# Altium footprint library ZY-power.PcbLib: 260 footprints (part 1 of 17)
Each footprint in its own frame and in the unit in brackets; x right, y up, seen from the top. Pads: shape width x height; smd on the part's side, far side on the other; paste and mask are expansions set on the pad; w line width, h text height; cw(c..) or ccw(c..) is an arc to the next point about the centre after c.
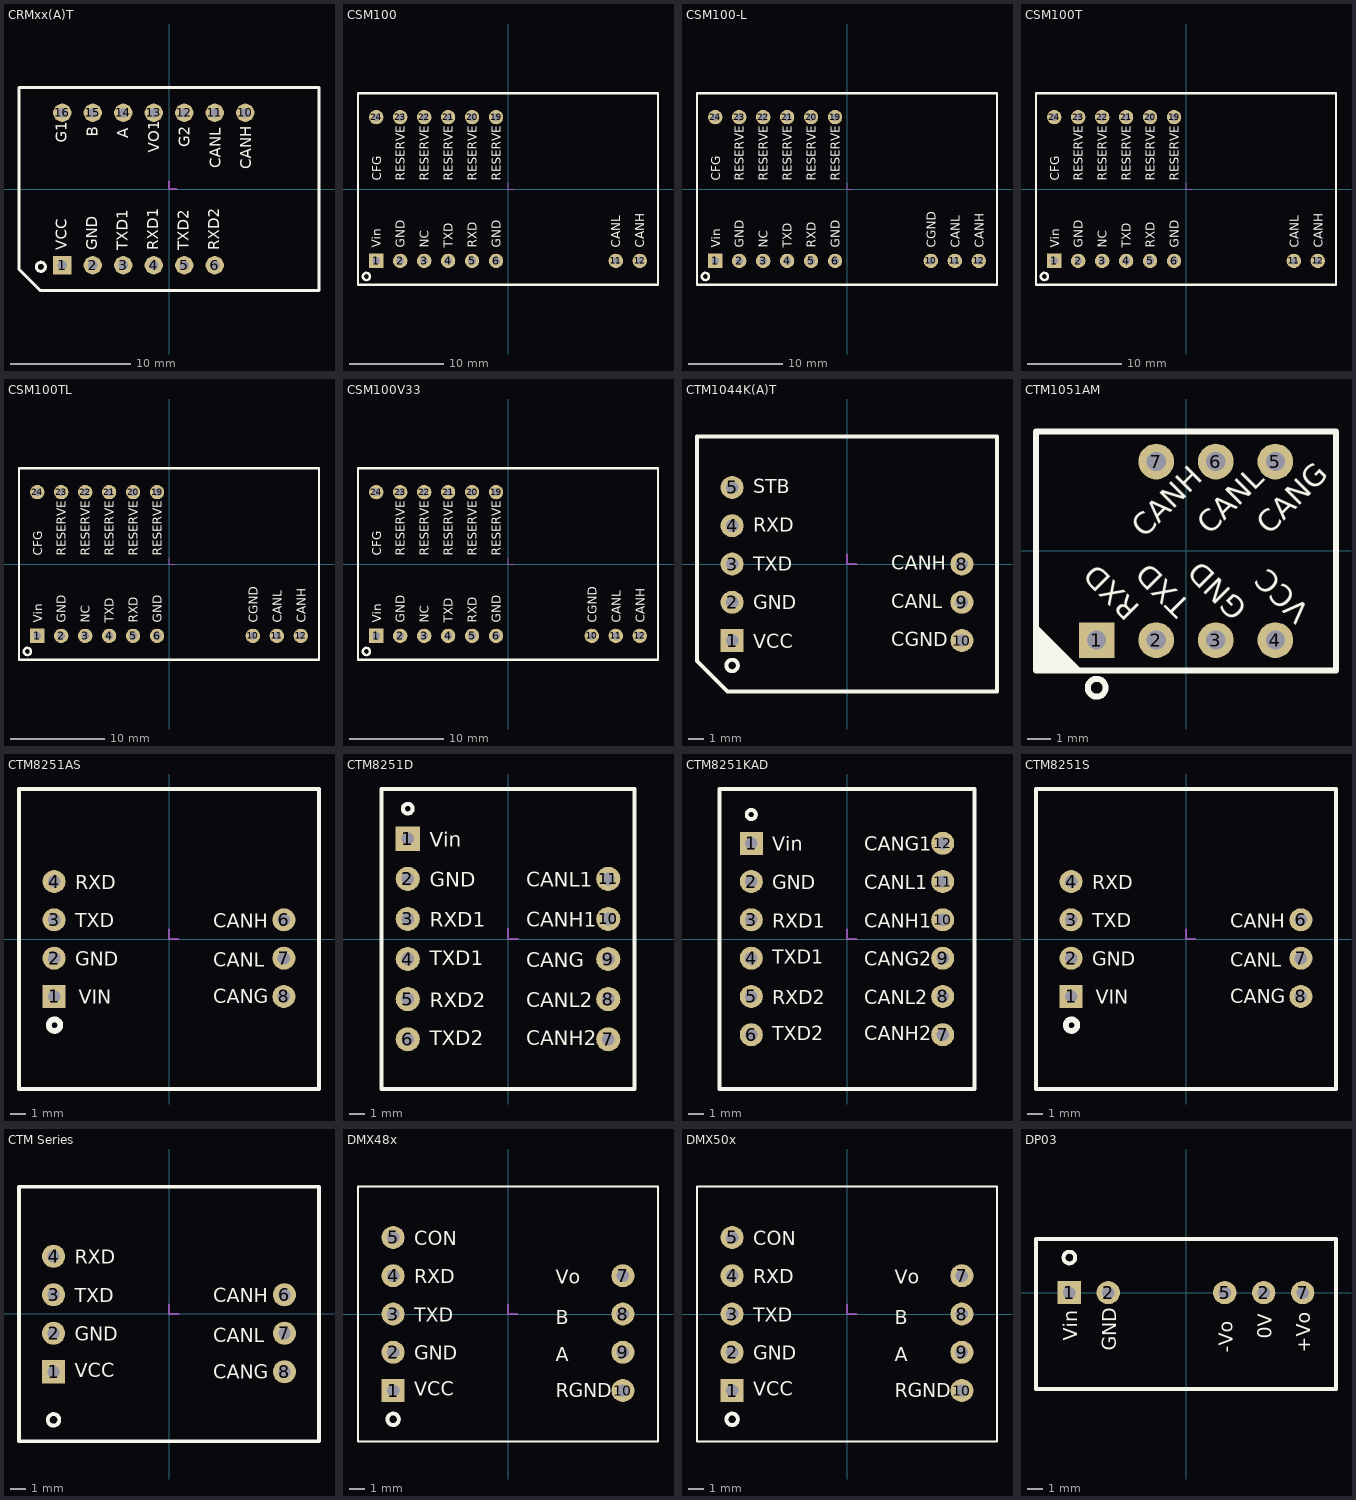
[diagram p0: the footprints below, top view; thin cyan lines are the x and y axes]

## CRMxx(A)T [mil]
height 279.53
pads (13):
  rect 60x60 hole 32: 1(-350,-250)
  round 60 hole 32: 2(-250,-250) 3(-150,-250) 4(-50,-250) 5(50,-250) 6(150,-250) 10(250,250) 11(150,250) 12(50,250) 13(-50,250) 14(-150,250) 15(-250,250) 16(-350,250)
Top Overlay:
  circle w10: c-420,-255 r15
  lines w10: -491.73,-263.27 -422.32,-332.68 491.73,-332.68 491.73,332.68 -491.73,332.68 -491.73,-263.27
  text "G1" at -335,152.07 h36
  text "B" at -234.17,170.58 h36
  text "A" at -133.33,167.15 h36
  text "VO1" at -32.5,118.13 h36
  text "G2" at 68.33,136.64 h36
  text "CANL" at 169.17,68.43 h36
  text "RXD2" at 165,-200 h36
  text "TXD2" at 65,-200 h36
  text "RXD1" at -35,-200 h36
  text "TXD1" at -135,-200 h36
  text "GND" at -235,-200 h36
  text "CANH" at 270,65 h36
  text "VCC" at -335,-200 h36
Mechanical 15:
  lines w5: 0,25 0,0 25,0

## CSM100 [mil] "嵌入式CAN-bus接口芯片"
height 370.08
pads (14):
  rect 60x60 hole 32: 1(-550,-300)
  round 60 hole 32: 2(-450,-300) 3(-350,-300) 4(-250,-300) 5(-150,-300) 6(-50,-300) 11(450,-300) 12(550,-300) 19(-50,300) 20(-150,300) 21(-250,300) 22(-350,300) 23(-450,300) 24(-550,300)
Top Overlay:
  circle w10: c-590.98,-365 r15
  lines w10: -625.98,-399.61 625.98,-399.61 625.98,399.61 -625.98,399.61 -625.98,-399.61
  text "Vin" at -531,-245 h36
  text "GND" at -431,-245 h36
  text "NC" at -331,-245 h36
  text "TXD" at -231,-245 h36
  text "RXD" at -131,-245 h36
  text "CANL" at 469,-245 h36
  text "CANH" at 569,-245 h36
  text "RESERVE" at -30,35 h36
  text "GND" at -31,-245 h36
  text "RESERVE" at -130,35 h36
  text "RESERVE" at -230,35 h36
  text "RESERVE" at -330,35 h36
  text "CFG" at -530,35 h36
  text "RESERVE" at -430,35 h36
Mechanical 15:
  lines w5: 0,25 0,0 25,0

## CSM100-L [mil]
pads (15):
  rect 60x60 hole 32: 1(-550,-300)
  round 60 hole 32: 2(-450,-300) 3(-350,-300) 4(-250,-300) 5(-150,-300) 6(-50,-300) 10(350,-300) 11(450,-300) 12(550,-300) 19(-50,300) 20(-150,300) 21(-250,300) 22(-350,300) 23(-450,300) 24(-550,300)
Top Overlay:
  circle w10: c-590.98,-365 r15
  lines w10: -625.98,-399.61 -625.98,399.61 625.98,399.61 625.98,-399.61 -625.98,-399.61
  text "CGND" at 370,-245 h36
  text "CFG" at -530,35 h36
  text "RESERVE" at -330,35 h36
  text "RESERVE" at -230,35 h36
  text "RESERVE" at -130,35 h36
  text "GND" at -30,-245 h36
  text "RESERVE" at -30,35 h36
  text "CANH" at 570,-245 h36
  text "CANL" at 470,-245 h36
  text "RXD" at -130,-245 h36
  text "TXD" at -230,-245 h36
  text "NC" at -330,-245 h36
  text "GND" at -430,-245 h36
  text "Vin" at -530,-245 h36
  text "RESERVE" at -430,35 h36
Mechanical 15:
  lines w5: 0,25 0,0 25,0

## CSM100T [mil]
pads (14):
  rect 60x60 hole 32: 1(-550,-300)
  round 60 hole 32: 2(-450,-300) 3(-350,-300) 4(-250,-300) 5(-150,-300) 6(-50,-300) 11(450,-300) 12(550,-300) 19(-50,300) 20(-150,300) 21(-250,300) 22(-350,300) 23(-450,300) 24(-550,300)
Top Overlay:
  circle w10: c-590.98,-365 r15
  lines w10: -625.98,-399.61 625.98,-399.61 625.98,399.61 -625.98,399.61 -625.98,-399.61
  text "Vin" at -530,-245 h36
  text "GND" at -430,-245 h36
  text "NC" at -330,-245 h36
  text "TXD" at -230,-245 h36
  text "RXD" at -130,-245 h36
  text "CANL" at 470,-245 h36
  text "CANH" at 570,-245 h36
  text "RESERVE" at -30,35 h36
  text "GND" at -30,-245 h36
  text "RESERVE" at -130,35 h36
  text "RESERVE" at -230,35 h36
  text "RESERVE" at -330,35 h36
  text "CFG" at -530,35 h36
  text "RESERVE" at -430,35 h36
Mechanical 15:
  lines w5: 0,25 0,0 25,0

## CSM100TL [mil]
height 255.91
pads (15):
  rect 60x60 hole 32: 1(-550,-300)
  round 60 hole 32: 2(-450,-300) 3(-350,-300) 4(-250,-300) 5(-150,-300) 6(-50,-300) 10(350,-300) 11(450,-300) 12(550,-300) 19(-50,300) 20(-150,300) 21(-250,300) 22(-350,300) 23(-450,300) 24(-550,300)
Top Overlay:
  circle w10: c-590.98,-365 r15
  lines w10: -625.98,-399.61 625.98,-399.61 625.98,399.61 -625.98,399.61 -625.98,-399.61
  text "RESERVE" at -430,35 h36
  text "Vin" at -530,-245 h36
  text "GND" at -430,-245 h36
  text "NC" at -330,-245 h36
  text "TXD" at -230,-245 h36
  text "RXD" at -130,-245 h36
  text "CANL" at 470,-245 h36
  text "CANH" at 570,-245 h36
  text "RESERVE" at -30,35 h36
  text "GND" at -30,-245 h36
  text "RESERVE" at -130,35 h36
  text "RESERVE" at -230,35 h36
  text "RESERVE" at -330,35 h36
  text "CFG" at -530,35 h36
  text "CGND" at 370,-245 h36
Mechanical 15:
  lines w5: 0,25 0,0 25,0

## CSM100V33 [mil]
pads (15):
  rect 60x60 hole 32: 1(-550,-300)
  round 60 hole 32: 2(-450,-300) 3(-350,-300) 4(-250,-300) 5(-150,-300) 6(-50,-300) 10(350,-300) 11(450,-300) 12(550,-300) 19(-50,300) 20(-150,300) 21(-250,300) 22(-350,300) 23(-450,300) 24(-550,300)
Top Overlay:
  circle w10: c-590.98,-365 r15
  lines w10: -625.98,-399.61 625.98,-399.61 625.98,399.61 -625.98,399.61 -625.98,-399.61
  text "RESERVE" at -430,35 h36
  text "Vin" at -530,-245 h36
  text "GND" at -430,-245 h36
  text "NC" at -330,-245 h36
  text "TXD" at -230,-245 h36
  text "RXD" at -130,-245 h36
  text "CANL" at 470,-245 h36
  text "CANH" at 570,-245 h36
  text "RESERVE" at -30,35 h36
  text "GND" at -30,-245 h36
  text "RESERVE" at -130,35 h36
  text "RESERVE" at -230,35 h36
  text "RESERVE" at -330,35 h36
  text "CFG" at -530,35 h36
  text "CGND" at 370,-245 h36
Mechanical 15:
  lines w5: 0,25 0,0 25,0

## CTM1044K(A)T [mil]
height 277.56
pads (8):
  rect 60x60 hole 32: 1(-300,-200)
  round 60 hole 32: 2(-300,-100) 3(-300,0) 4(-300,100) 5(-300,200) 8(300,0) 9(300,-100) 10(300,-200)
Top Overlay:
  circle w10: c-300,-265 r15
  lines w10: -391.73,-253.27 -391.73,332.68 391.73,332.68 391.73,-332.68 -312.32,-332.68 -391.73,-253.27
  text "VCC" at -245,-220 h36
  text "GND" at -245,-118.75 h36
  text "TXD" at -245,-17.5 h36
  text "RXD" at -245,83.75 h36
  text "CANH" at 115,-15 h36
  text "CANL" at 115,-115 h36
  text "CGND" at 115,-215 h36
  text "STB" at -245,185 h36
Mechanical 15:
  lines w5: 0,25 0,0 25,0

## CTM1051AM [mil]
height 303.15
pads (7):
  rect 60x60 hole 32: 1(-150,-150)
  round 60 hole 32: 2(-50,-150) 3(50,-150) 4(150,-150) 5(150,150) 6(50,150) 7(-50,150)
Top Overlay:
  circle w10: c-150,-230 r15
  region: -251.97,-200.79 -174.21,-200.79 -251.97,-123.04
  lines w10: -251.97,-200.79 251.97,-200.79 251.97,200.79 -251.97,200.79 -251.97,-200.79
  text "VCC" at 210,-100 h36
  text "GND" at 105,-95 h36
  text "TXD" at 10,-90 h36
  text "RXD" at -75,-95 h36
  text "CANH" at -70,20 h36
  text "CANL" at 40,25 h36
  text "CANG" at 140,25 h36

## CTM8251AS [mil]
height 196.85
pads (7):
  rect 60x60 hole 32: 1(-300,-150)
  round 60 hole 32: 2(-300,-50) 3(-300,50) 4(-300,150) 6(300,50) 7(300,-50) 8(300,-150)
Top Overlay:
  circle w15: c-299,-225 r15
  lines w10: -391.73,-391.73 -391.73,391.73 391.73,391.73 391.73,-391.73 -391.73,-391.73
  text "CANG" at 115,-168 h36
  text "CANL" at 115,-73 h36
  text "CANH" at 115,30 h36
  text "RXD" at -245,130 h36
  text "TXD" at -245,30.33 h36
  text "GND" at -245,-69.33 h36
  text "VIN" at -236,-169 h36
Mechanical 15:
  lines w5: 0,25 0,0 25,0

## CTM8251D [mil]
pads (11):
  rect 60x60 hole 32: 1(-250,250)
  round 60 hole 32: 2(-250,150) 3(-250,50) 4(-250,-50) 5(-250,-150) 6(-250,-250) 7(250,-250) 8(250,-150) 9(250,-50) 10(250,50) 11(250,150)
Top Overlay:
  circle w10: c-250,325 r12
  lines w10: -314.96,-374.02 -314.96,374.02 314.96,374.02 314.96,-374.02 -314.96,-374.02
  text "RXD2" at -195,-170 h36
  text "TXD2" at -195,-265 h36
  text "CANH2" at 45,-265 h36
  text "CANL2" at 45,-170 h36
  text "TXD1" at -195,-65 h36
  text "RXD1" at -195,30 h36
  text "GND" at -195,130 h36
  text "Vin" at -195,230 h36
  text "CANL1" at 45,130 h36
  text "CANH1" at 45,30 h36
  text "CANG" at 45,-70 h36
Mechanical 15:
  lines w5: 0,25 0,0 25,0

## CTM8251KAD [mil]
pads (12):
  rect 60x60 hole 32: 1(-250,250)
  round 60 hole 32: 2(-250,150) 3(-250,50) 4(-250,-50) 5(-250,-150) 6(-250,-250) 7(250,-250) 8(250,-150) 9(250,-50) 10(250,50) 11(250,150) 12(250,250)
Top Overlay:
  circle w10: c-250,325 r12
  lines w10: -332.68,-391.73 -332.68,391.73 332.68,391.73 332.68,-391.73 -332.68,-391.73
  text "RXD2" at -195,-170 h36
  text "TXD2" at -195,-265 h36
  text "CANH2" at 45,-265 h36
  text "CANL2" at 45,-170 h36
  text "TXD1" at -195,-65 h36
  text "RXD1" at -195,30 h36
  text "GND" at -195,130 h36
  text "Vin" at -195,230 h36
  text "CANL1" at 45,130 h36
  text "CANH1" at 45,30 h36
  text "CANG2" at 45,-70 h36
  text "CANG1" at 45,230 h36
Mechanical 15:
  lines w5: 0,25 0,0 25,0

## CTM8251S [mil]
height 196.85
pads (7):
  rect 60x60 hole 32: 1(-300,-150)
  round 60 hole 32: 2(-300,-50) 3(-300,50) 4(-300,150) 6(300,50) 7(300,-50) 8(300,-150)
Top Overlay:
  circle w15: c-299,-225 r15
  lines w10: -391.73,-391.73 -391.73,391.73 391.73,391.73 391.73,-391.73 -391.73,-391.73
  text "CANG" at 115,-168 h36
  text "CANL" at 115,-73 h36
  text "CANH" at 115,30 h36
  text "RXD" at -245,130 h36
  text "TXD" at -245,30.33 h36
  text "GND" at -245,-69.33 h36
  text "VIN" at -236,-169 h36
Mechanical 15:
  lines w5: 0,25 0,0 25,0

## CTM Series [mil] "CTM系列隔离CAN收发器(CTM8250\8251\1040\1050\8250T\8251T\1040T\1050T\8251A\8251AT)"
height 271.65
pads (7):
  rect 60x60 hole 32: 1(-300,-150)
  round 60 hole 32: 2(-300,-50) 3(-300,50) 4(-300,150) 6(300,50) 7(300,-50) 8(300,-150)
Top Overlay:
  circle w10: c-300,-275 r15
  lines w10: -389.76,-330.71 389.76,-330.71 389.76,330.71 -389.76,330.71 -389.76,-330.71
  text "VCC" at -245,-164 h36
  text "GND" at -245,-69 h36
  text "TXD" at -245,30 h36
  text "RXD" at -245,130 h36
  text "CANH" at 115,30 h36
  text "CANL" at 115,-73 h36
  text "CANG" at 115,-168 h36
Mechanical 15:
  lines w5: 0,25 0,0 25,0

## DMX48x [mil]
height 295.28
pads (9):
  rect 60x60 hole 32: 1(-300,-200)
  round 60 hole 32: 2(-300,-100) 3(-300,0) 4(-300,100) 5(-300,200) 7(300,100) 8(300,0) 9(300,-100) 10(300,-200)
Top Overlay:
  circle w10: c-300,-275 r15
  lines w5: -391.73,-332.68 -391.73,332.68 391.73,332.68 391.73,-332.68 -391.73,-332.68
  text "RGND" at 125,-218 h36
  text "A" at 125,-123 h36
  text "B" at 125,-27 h36
  text "Vo" at 125,79 h36
  text "CON" at -245,180 h36
  text "RXD" at -245,80 h36
  text "TXD" at -245,-20 h36
  text "GND" at -245,-119 h36
  text "VCC" at -245,-214 h36
Mechanical 15:
  lines w5: 0,25 0,0 25,0

## DMX50x [mil]
height 295.28
pads (9):
  rect 60x60 hole 32: 1(-300,-200)
  round 60 hole 32: 2(-300,-100) 3(-300,0) 4(-300,100) 5(-300,200) 7(300,100) 8(300,0) 9(300,-100) 10(300,-200)
Top Overlay:
  circle w10: c-300,-275 r15
  lines w5: -391.73,-332.68 -391.73,332.68 391.73,332.68 391.73,-332.68 -391.73,-332.68
  text "RGND" at 125,-218 h36
  text "A" at 125,-123 h36
  text "B" at 125,-27 h36
  text "Vo" at 125,79 h36
  text "CON" at -245,180 h36
  text "RXD" at -245,80 h36
  text "TXD" at -245,-20 h36
  text "GND" at -245,-119 h36
  text "VCC" at -245,-214 h36
Mechanical 15:
  lines w5: 0,25 0,0 25,0

## DP03 [mil]
height 492.13
pads (5):
  rect 60x60 hole 32: 1(-300,0)
  round 60 hole 32: 2(-200,0) 2(199.74,0) 5(99.74,0) 7(300,0)
Top Overlay:
  circle w10: c-300,90 r15
  lines w10: -385.83,-248.03 -385.83,137.8 385.83,137.8 385.83,-248.03 -385.83,-248.03
  text "Vin" at -280,-123.29 h36
  text "GND" at -180,-150 h36
  text "-Vo" at 120,-155 h36
  text "+Vo" at 320,-155 h36
  text "0V" at 220,-118.67 h36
